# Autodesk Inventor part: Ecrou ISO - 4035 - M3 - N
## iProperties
Created: 2011-01
Part Number: Ecrou ISO - 4035 - M3 - N
Document SubType Name: Modeling
Designer: eric
Density: 1 g/cm^3
Mass: 0.0375366 g
Surface Area: 0.867973 cm^2
Volume: 0.0375366 cm^3
Author: eric
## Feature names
1. Base1
